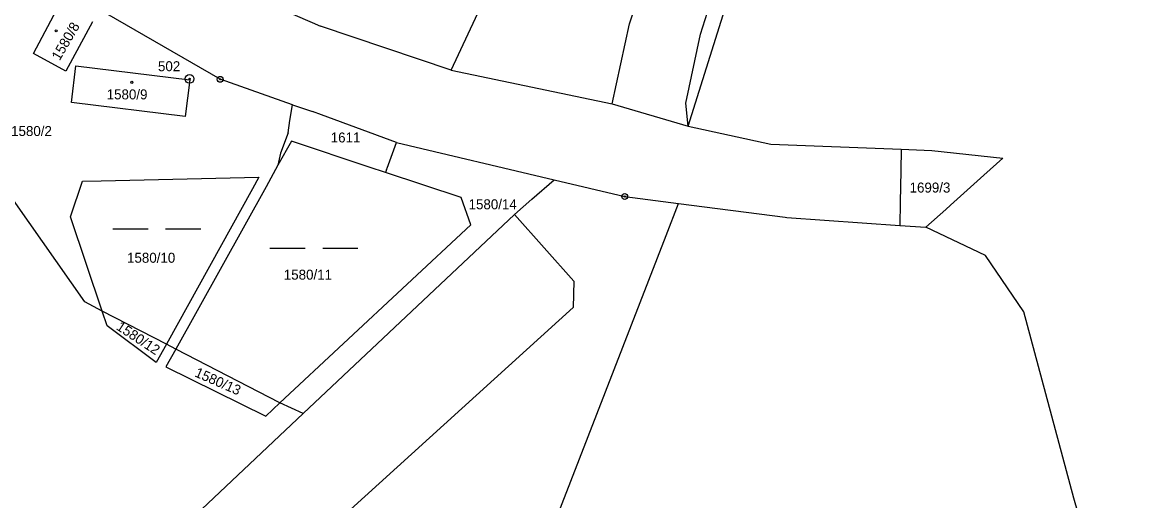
# Model space of a CAD drawing. Extents: x -763296 to -761805, y -1153670 to -1152034.
# Drawn here: x -762375.6 to -762186.4, y -1152539 to -1152457.5 of the extents above; entities that cross this region are included whole.
import ezdxf

# ---------------------------------------------------------------- set-up
doc = ezdxf.new("R2010")
doc.units = 0
for name, color, linetype in [('Vrstva 1', 7, 'Continuous'), ('Vrstva 13', 7, 'Continuous'), ('Vrstva 17', 7, 'Continuous'), ('Vrstva 18', 7, 'Continuous'), ('Vrstva 19', 7, 'Continuous'), ('Vrstva 24', 7, 'Continuous'), ('Vrstva 25', 7, 'Continuous')]:
    doc.layers.add(name, color=color, linetype=linetype)

msp = doc.modelspace()

# ---------------------------------------------------------------- linework, layer by layer
at = {"layer": 'Vrstva 1'}
for p, q in [((-762259.95, -1152459.53), (-762222.86, -1152344.39)), ((-762302.43, -1152465.69), (-762282.46, -1152422.96)), ((-762272.05, -1152457.76), (-762266.21, -1152440.18)), ((-762341.83, -1152467.23), (-762370.42, -1152450.7)), ((-762373.67, -1152462.84), (-762369.24, -1152454.47)), ((-762363.62, -1152457.44), (-762368.12, -1152465.82)), ((-762329.43, -1152456.14), (-762326.14, -1152457.54)), ((-762326.14, -1152457.54), (-762324.72, -1152458.15)), ((-762275, -1152471.39), (-762272.05, -1152457.76)), ((-762302.43, -1152465.69), (-762324.72, -1152458.15)), ((-762262.43, -1152471.27), (-762259.95, -1152459.53)), ((-762368.12, -1152465.82), (-762373.67, -1152462.84)), ((-762367.19, -1152471.2), (-762366.42, -1152464.96)), ((-762366.42, -1152464.96), (-762347.02, -1152467.31)), ((-762347.02, -1152467.31), (-762347.78, -1152473.58)), ((-762329.51, -1152471.59), (-762341.83, -1152467.23)), ((-762302.43, -1152465.69), (-762275, -1152471.39)), ((-762347.78, -1152473.58), (-762367.19, -1152471.2)), ((-762329.93, -1152474.27), (-762329.51, -1152471.59)), ((-762329.51, -1152471.59), (-762326.09, -1152472.7)), ((-762324.54, -1152473.27), (-762326.09, -1152472.7)), ((-762275, -1152471.39), (-762262.04, -1152475.19)), ((-762262.04, -1152475.19), (-762262.43, -1152471.27)), ((-762330.26, -1152476.34), (-762329.93, -1152474.27)), ((-762311.78, -1152477.99), (-762324.54, -1152473.27)), ((-762330.26, -1152476.34), (-762331.53, -1152479.83)), ((-762329.67, -1152477.74), (-762331.97, -1152481.87)), ((-762316.41, -1152482.17), (-762329.67, -1152477.74)), ((-762313.38, -1152482.35), (-762311.78, -1152477.99)), ((-762311.78, -1152477.99), (-762284.89, -1152484.35)), ((-762331.53, -1152479.83), (-762331.97, -1152481.87)), ((-762225.73, -1152479.11), (-762225.79, -1152482.85)), ((-762331.97, -1152481.87), (-762334, -1152485.52)), ((-762313.65, -1152483.09), (-762316.41, -1152482.17)), ((-762313.46, -1152482.58), (-762313.38, -1152482.35)), ((-762362.14, -1152484.5), (-762335.22, -1152483.88)), ((-762335.22, -1152483.88), (-762336.34, -1152485.9)), ((-762313.46, -1152482.58), (-762313.65, -1152483.09)), ((-762300.75, -1152487.39), (-762313.65, -1152483.09)), ((-762288.68, -1152487.65), (-762284.89, -1152484.35)), ((-762284.89, -1152484.35), (-762272.86, -1152487.19)), ((-762225.79, -1152482.85), (-762225.88, -1152488.17)), ((-762364.92, -1152505.15), (-762379.39, -1152484.58)), ((-762367.34, -1152490.65), (-762365.29, -1152484.57)), ((-762365.29, -1152484.57), (-762362.14, -1152484.5)), ((-762336.34, -1152485.9), (-762350.99, -1152512.36)), ((-762334, -1152485.52), (-762349.39, -1152513.18)), ((-762299.12, -1152492.02), (-762300.75, -1152487.39)), ((-762291.65, -1152490.24), (-762288.68, -1152487.65)), ((-762272.86, -1152487.19), (-762263.68, -1152488.38)), ((-762225.88, -1152488.17), (-762225.95, -1152492.16)), ((-762265.79, -1152493.82), (-762263.68, -1152488.38)), ((-762263.68, -1152488.38), (-762245.5, -1152490.74)), ((-762361.92, -1152506.7), (-762367.34, -1152490.65)), ((-762291.65, -1152490.24), (-762327.69, -1152524.15)), ((-762281.54, -1152501.6), (-762291.65, -1152490.24)), ((-762245.5, -1152490.74), (-762245.24, -1152490.77)), ((-762245.24, -1152490.77), (-762225.95, -1152492.16)), ((-762331.66, -1152522.36), (-762299.12, -1152492.02)), ((-762286.79, -1152547.88), (-762265.79, -1152493.82)), ((-762225.95, -1152492.16), (-762221.54, -1152492.44)), ((-762281.54, -1152501.6), (-762281.64, -1152506.08)), ((-762361.92, -1152506.7), (-762364.92, -1152505.15)), ((-762361.07, -1152509.23), (-762361.92, -1152506.7)), ((-762350.99, -1152512.36), (-762361.92, -1152506.7)), ((-762281.64, -1152506.08), (-762334.74, -1152554.22)), ((-762352.73, -1152515.5), (-762361.07, -1152509.23)), ((-762350.99, -1152512.36), (-762352.73, -1152515.5)), ((-762349.39, -1152513.18), (-762350.99, -1152512.36)), ((-762349.39, -1152513.18), (-762351.09, -1152516.23)), ((-762331.66, -1152522.36), (-762349.39, -1152513.18)), ((-762351.09, -1152516.23), (-762334.06, -1152524.6)), ((-762334.06, -1152524.6), (-762331.66, -1152522.36)), ((-762327.69, -1152524.15), (-762331.66, -1152522.36)), ((-762357.84, -1152552.56), (-762327.69, -1152524.15))]:
    msp.add_line(p, q, dxfattribs=at)
at = {"layer": 'Vrstva 13'}
for p, q in [((-762262.04, -1152475.19), (-762215.11, -1152325.64)), ((-762262.04, -1152475.19), (-762247.97, -1152478.3)), ((-762247.97, -1152478.3), (-762225.73, -1152479.11)), ((-762225.73, -1152479.11), (-762220.51, -1152479.37)), ((-762220.51, -1152479.37), (-762208.38, -1152480.64)), ((-762211.62, -1152483.55), (-762208.38, -1152480.64)), ((-762217.34, -1152488.68), (-762211.62, -1152483.55)), ((-762221.54, -1152492.44), (-762218.14, -1152489.4)), ((-762218.14, -1152489.4), (-762217.34, -1152488.68)), ((-762211.36, -1152497.26), (-762221.54, -1152492.44)), ((-762204.84, -1152506.84), (-762211.36, -1152497.26)), ((-762196.29, -1152538.57), (-762204.84, -1152506.84)), ((-762186.41, -1152572.39), (-762196.29, -1152538.57))]:
    msp.add_line(p, q, dxfattribs=at)
at = {"layer": 'Vrstva 24'}
for centre, radius in [((-762347.04, -1152467.16), 0.75), ((-762347.04, -1152467.16), 0.1), ((-762341.83, -1152467.23), 0.5), ((-762341.83, -1152467.23), 0.1), ((-762272.86, -1152487.19), 0.5), ((-762272.86, -1152487.19), 0.1)]:
    msp.add_circle(centre, radius, dxfattribs=at)
at = {"layer": 'Vrstva 25'}
for p, q in [((-762360.13, -1152492.7), (-762354.13, -1152492.7)), ((-762351.13, -1152492.7), (-762345.13, -1152492.7)), ((-762333.35, -1152496), (-762327.35, -1152496)), ((-762324.35, -1152496), (-762318.35, -1152496))]:
    msp.add_line(p, q, dxfattribs=at)
for centre in [(-762369.77, -1152458.99), (-762356.88, -1152467.75)]:
    msp.add_circle(centre, 0.175, dxfattribs=at)

# ---------------------------------------------------------------- texts
at = {"layer": 'Vrstva 17'}
msp.add_text('502', height=1.7, dxfattribs=at).set_placement((-762352.431, -1152465.85))
at = {"layer": 'Vrstva 18'}
for s, p in [('1580/2', (-762377.468, -1152476.89)), ('1611', (-762322.979, -1152477.99)), ('1699/3', (-762224.291, -1152486.52)), ('1580/14', (-762299.476, -1152489.37)), ('1580/10', (-762357.703, -1152498.48)), ('1580/11', (-762330.978, -1152501.36))]:
    msp.add_text(s, height=1.7, dxfattribs=at).set_placement(p)
for s, rotation, p in [('1580/12', 326.58594, (-762359.681, -1152509.748)), ('1580/13', 336.32623, (-762346.301, -1152517.802))]:
    msp.add_text(s, height=1.7, rotation=rotation, dxfattribs=at).set_placement(p)
at = {"layer": 'Vrstva 19'}
msp.add_text('1580/8', height=1.7, rotation=59.81679, dxfattribs=at).set_placement((-762369.198, -1152464.157))
msp.add_text('1580/9', height=1.7, dxfattribs=at).set_placement((-762361.175, -1152470.65))

doc.saveas('drawing.dxf')
